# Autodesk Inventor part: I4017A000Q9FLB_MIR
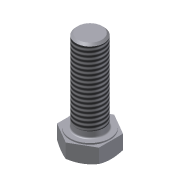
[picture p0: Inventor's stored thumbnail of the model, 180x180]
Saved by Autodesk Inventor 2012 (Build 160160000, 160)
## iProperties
Company: CAD-Verlag
Shininess: 64.0
Length Units: 11269
Angle Units: 11279
Time Units: 11290
Mass Units: 11283
Length Display Precision: 3
Angle Display Precision: 2
Compacted: True
Part Number: I4017A000Q9FLB_MIR
Document SubType Name: Modeling
Created: 2004-09
Material: Steel, Mild
Designer: Greiling
Manufacturer: Standard
Standards Organization: Custom
Density: 1 g/cm^3
Density: 0.0
Volumn: 0.0
Area: 0.0
PropertySet Name: Model Information
Control State: 0
Master: False
Checked Out: False
d28: 0,000 mm
Author: Jürgen Kronas
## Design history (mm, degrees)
node "Sechskantschraube DIN EN ISO 4017 - M12x35" dims "d0" = 10, "d28" = 0
  node "WorkPlane1"
  node "MSC_PF1"
  node "MSC_PT1"
  node "MSC_A1"
  node "WorkAxis1"
  node "WorkPoint1"
node "Volumenkörper1"
node "Volumenkörpern"
node "Oberflächenkörpern"
tag "Bezeichnung2"
feature "Volumenkörper1::Sechskantschraube DIN EN ISO 4017 - M12x35" dims "d0" = 10, "d28" = 0
